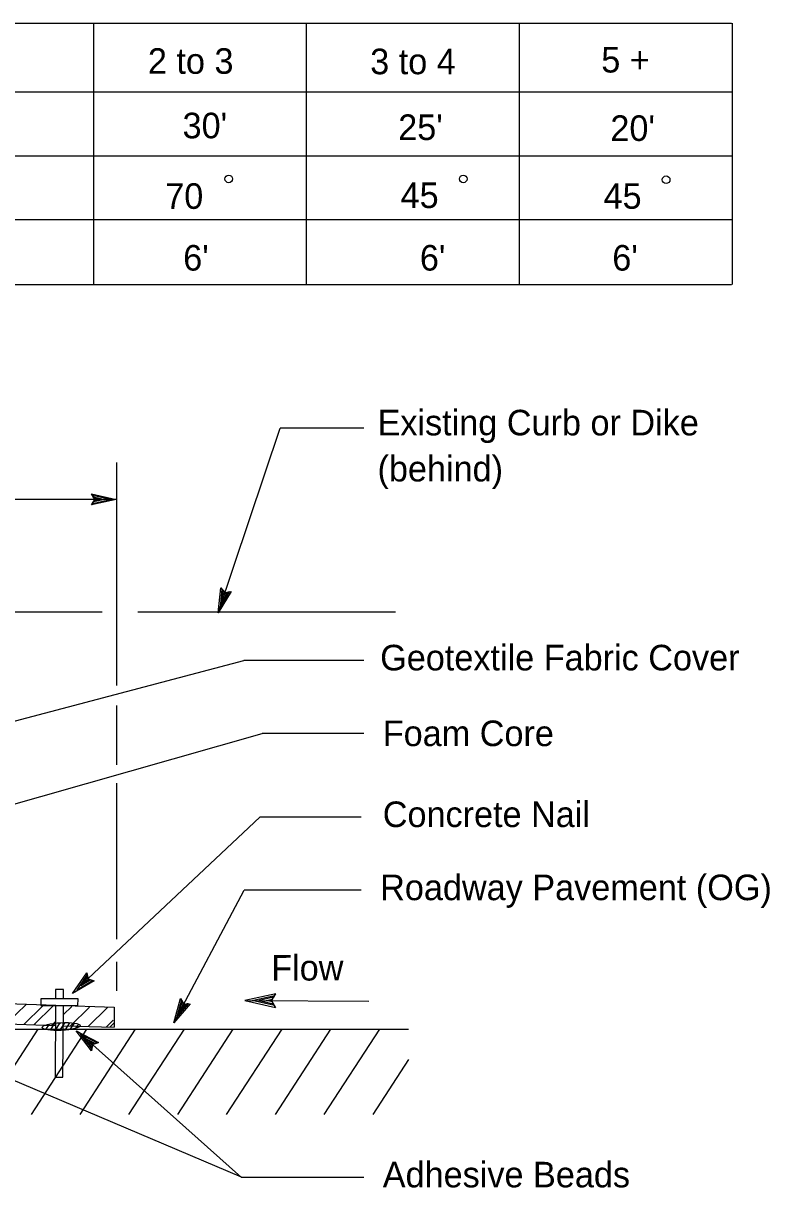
# Model space of a CAD drawing. Extents: x 6708945 to 6710368, y 1871409 to 1872338.
# Drawn here: x 6709846.1 to 6710021.1, y 1872053.9 to 1872327.1 of the extents above; entities that cross this region are included whole.
import ezdxf

# ---------------------------------------------------------------- set-up
doc = ezdxf.new("R2010")
doc.units = 0
for name, color, linetype in [('1 Control', 7, 'Continuous'), ('57 Undefined', 7, 'Continuous'), ('60 Nongeo Data', 7, 'Continuous')]:
    doc.layers.add(name, color=color, linetype=linetype)

msp = doc.modelspace()

# ---------------------------------------------------------------- linework, layer by layer
at = {"layer": '1 Control'}
for p, q in [((6709905.27, 1872099.41), (6709905.27, 1872099.41)), ((6709898.06, 1872097.83), (6709898.06, 1872097.83)), ((6709905.26, 1872096.21), (6709905.26, 1872096.21))]:
    msp.add_line(p, q, dxfattribs=at)
msp.add_lwpolyline([(6709905.27, 1872099.41), (6709898.06, 1872097.83), (6709905.26, 1872096.21), (6709905, 1872096.63), (6709899.73, 1872097.82), (6709905.01, 1872098.99), (6709904.76, 1872098.56), (6709901.38, 1872097.82), (6709904.75, 1872097.06), (6709904.49, 1872097.49), (6709903.04, 1872097.81), (6709904.5, 1872098.14), (6709904.3, 1872097.81), (6709905.26, 1872096.21), (6709904.3, 1872097.81)], close=True, dxfattribs=at)
at = {"layer": '57 Undefined'}
for p, q in [((6709550.84, 1872327.05), (6710012.14, 1872327.05)), ((6709862.61, 1872265.76), (6709862.61, 1872327.05)), ((6709912.53, 1872265.76), (6709912.53, 1872327.05)), ((6709962.45, 1872265.76), (6709962.45, 1872327.05)), ((6710012.37, 1872265.76), (6710012.37, 1872327.05)), ((6709627.72, 1872310.96), (6709893.03, 1872310.96)), ((6709649.9, 1872310.96), (6709915.21, 1872310.96)), ((6709863.83, 1872311), (6709940.81, 1872311)), ((6709914.87, 1872311), (6709991.86, 1872311)), ((6709915.93, 1872311), (6710012.14, 1872311)), ((6709550.84, 1872295.98), (6710012.14, 1872295.98)), ((6709550.73, 1872281.01), (6709916.77, 1872281.01)), ((6709855.9, 1872281.06), (6709859.86, 1872281.06)), ((6709915.93, 1872281.05), (6710012.14, 1872281.05)), ((6709916.63, 1872281.05), (6709993.62, 1872281.05)), ((6709550.84, 1872265.76), (6710012.14, 1872265.76)), ((6709891.8, 1872188.72), (6709906.29, 1872232.1)), ((6709925.94, 1872232.1), (6709906.29, 1872232.1)), ((6709867.99, 1872182.94), (6709867.99, 1872224.04)), ((6709867.87, 1872215.36), (6709800.03, 1872215.36)), ((6709867.99, 1872171.7), (6709867.99, 1872186.66)), ((6709768.13, 1872143.4), (6709897.78, 1872177.59)), ((6709925.94, 1872177.59), (6709897.78, 1872177.59)), ((6709867.99, 1872153.09), (6709867.99, 1872167.05)), ((6709760.18, 1872120.13), (6709902.07, 1872160.44)), ((6709925.94, 1872160.44), (6709902.07, 1872160.44)), ((6709867.99, 1872112.2), (6709867.99, 1872148.76)), ((6709859.97, 1872101.75), (6709901.55, 1872140.84)), ((6709925.32, 1872140.84), (6709901.55, 1872140.84)), ((6709881.39, 1872092.57), (6709897.85, 1872123.69)), ((6709925.32, 1872123.69), (6709897.85, 1872123.69)), ((6709867.99, 1872100.09), (6709867.99, 1872106.88)), ((6709897.25, 1872056.34), (6709816.57, 1872090.62)), ((6709897.27, 1872056.32), (6709858.76, 1872090.59)), ((6709925.94, 1872056.32), (6709897.27, 1872056.32))]:
    msp.add_line(p, q, dxfattribs=at)
for centre in [(6709894.25, 1872290.55), (6709949.25, 1872290.55), (6709996.84, 1872290.34)]:
    msp.add_circle(centre, 0.897, dxfattribs=at)
at = {"layer": '60 Nongeo Data'}
for p, q in [((6709862.11, 1872216.65), (6709862.11, 1872216.65)), ((6709862.11, 1872214.08), (6709862.11, 1872214.08)), ((6709867.87, 1872215.36), (6709867.87, 1872215.36)), ((6709892.41, 1872194.59), (6709892.41, 1872194.59)), ((6709894.85, 1872193.78), (6709894.85, 1872193.78)), ((6709864.57, 1872188.9), (6709805.77, 1872188.9)), ((6709933.37, 1872188.9), (6709872.97, 1872188.9)), ((6709891.8, 1872188.72), (6709891.8, 1872188.72)), ((6709860.96, 1872104.3), (6709860.96, 1872104.3)), ((6709862.72, 1872102.43), (6709862.72, 1872102.43)), ((6709857.64, 1872099.43), (6709857.64, 1872099.43)), ((6709816.28, 1872098.07), (6709867.42, 1872096.25)), ((6709846.76, 1872096.91), (6709842.25, 1872092.46)), ((6709850.67, 1872096.55), (6709846.22, 1872092.16)), ((6709853.05, 1872096.54), (6709848.66, 1872092.21)), ((6709857.45, 1872096.43), (6709855.54, 1872094.55)), ((6709882.96, 1872098.25), (6709882.96, 1872098.25)), ((6709885.22, 1872097.06), (6709885.22, 1872097.06)), ((6709898.56, 1872097.79), (6709927.08, 1872097.68)), ((6709861.58, 1872096.24), (6709857.12, 1872091.84)), ((6709865.81, 1872096.14), (6709861.32, 1872091.71)), ((6709867.42, 1872096.25), (6709867.39, 1872091.53)), ((6709795.95, 1872091.07), (6709936.43, 1872091.07)), ((6709814.06, 1872093.29), (6709853.57, 1872091.92)), ((6709849.45, 1872091.07), (6709836.44, 1872071.04)), ((6709860.9, 1872091.07), (6709847.89, 1872071.04)), ((6709850.63, 1872091.75), (6709850.46, 1872091.48)), ((6709852.12, 1872092.27), (6709851.3, 1872091.01)), ((6709853.39, 1872092.47), (6709852.34, 1872090.85)), ((6709853.52, 1872092.79), (6709852.62, 1872091.9)), ((6709854.61, 1872092.58), (6709853.45, 1872090.79)), ((6709853.56, 1872091.94), (6709853.5, 1872091.88)), ((6709855.78, 1872092.63), (6709854.6, 1872090.8)), ((6709855.57, 1872091.88), (6709867.39, 1872091.53)), ((6709856.91, 1872092.6), (6709855.79, 1872090.87)), ((6709858, 1872092.51), (6709857.03, 1872091.02)), ((6709858.99, 1872092.28), (6709858.35, 1872091.29)), ((6709872.34, 1872091.07), (6709859.34, 1872071.04)), ((6709867.18, 1872093.22), (6709865.53, 1872091.59)), ((6709867.34, 1872092.49), (6709866.4, 1872091.56)), ((6709883.79, 1872091.07), (6709870.78, 1872071.04)), ((6709881.39, 1872092.57), (6709881.39, 1872092.57)), ((6709895.24, 1872091.07), (6709882.23, 1872071.04)), ((6709906.68, 1872091.07), (6709893.68, 1872071.04)), ((6709918.13, 1872091.07), (6709905.12, 1872071.04)), ((6709929.58, 1872091.07), (6709916.57, 1872071.04)), ((6709858.5, 1872090.69), (6709858.5, 1872090.69)), ((6709862.1, 1872086.02), (6709862.1, 1872086.02)), ((6709863.74, 1872087.98), (6709863.74, 1872087.98)), ((6709936.43, 1872083.99), (6709928.02, 1872071.04))]:
    msp.add_line(p, q, dxfattribs=at)
for points in [[(6709862.11, 1872216.65), (6709867.87, 1872215.36), (6709862.11, 1872214.08), (6709862.31, 1872214.42), (6709866.53, 1872215.36), (6709862.31, 1872216.31), (6709862.51, 1872215.97), (6709865.22, 1872215.36), (6709862.52, 1872214.76), (6709862.72, 1872215.1), (6709863.89, 1872215.36), (6709862.72, 1872215.62), (6709862.88, 1872215.36), (6709862.11, 1872214.08), (6709862.88, 1872215.36)], [(6709894.85, 1872193.78), (6709891.8, 1872188.72), (6709892.41, 1872194.59), (6709892.67, 1872194.29), (6709892.22, 1872189.99), (6709894.46, 1872193.69), (6709894.07, 1872193.61), (6709892.64, 1872191.24), (6709892.93, 1872193.99), (6709893.19, 1872193.69), (6709893.06, 1872192.5), (6709893.68, 1872193.52), (6709893.38, 1872193.46), (6709892.41, 1872194.59), (6709893.38, 1872193.46)], [(6709862.72, 1872102.43), (6709857.64, 1872099.43), (6709860.96, 1872104.3), (6709861.05, 1872103.91), (6709858.61, 1872100.34), (6709862.34, 1872102.54), (6709861.95, 1872102.65), (6709859.57, 1872101.24), (6709861.13, 1872103.52), (6709861.21, 1872103.14), (6709860.54, 1872102.15), (6709861.57, 1872102.76), (6709861.28, 1872102.84), (6709860.96, 1872104.3), (6709861.28, 1872102.84)], [(6709858.91, 1872098.18), (6709850.18, 1872098.24), (6709850.17, 1872096.67), (6709858.9, 1872096.61)], [(6709885.22, 1872097.06), (6709881.39, 1872092.57), (6709882.96, 1872098.25), (6709883.16, 1872097.91), (6709882.01, 1872093.75), (6709884.83, 1872097.04), (6709884.43, 1872097.02), (6709882.63, 1872094.91), (6709883.37, 1872097.57), (6709883.57, 1872097.23), (6709883.26, 1872096.08), (6709884.03, 1872096.99), (6709883.73, 1872096.98), (6709882.96, 1872098.25), (6709883.73, 1872096.98)], [(6709862.1, 1872086.02), (6709858.5, 1872090.69), (6709863.75, 1872087.98), (6709863.37, 1872087.85), (6709859.53, 1872089.84), (6709862.17, 1872086.41), (6709862.23, 1872086.8), (6709860.54, 1872088.99), (6709862.99, 1872087.72), (6709862.62, 1872087.59), (6709861.56, 1872088.14), (6709862.29, 1872087.19), (6709862.34, 1872087.5), (6709863.75, 1872087.98), (6709862.34, 1872087.5)]]:
    msp.add_lwpolyline(points, close=True, dxfattribs=at)
for points in [[(6709855.5, 1872098.2), (6709855.52, 1872100.36), (6709853.65, 1872100.37), (6709853.64, 1872098.21)], [(6709853.63, 1872096.68), (6709853.52, 1872079.81), (6709855.38, 1872079.8), (6709855.49, 1872096.61)]]:
    msp.add_lwpolyline(points, dxfattribs=at)
msp.add_ellipse((6709854.94, 1872091.71), major_axis=(4.48, 0.22), ratio=0.199687, dxfattribs=at)

# ---------------------------------------------------------------- texts
at = {"layer": '57 Undefined'}
for s, p in [('2 to 3', (6709875.3, 1872315.2)), ('3 to 4', (6709927.43, 1872315.1)), ('5 +', (6709981.63, 1872315.5)), ("30'", (6709883.43, 1872300.07)), ("25'", (6709934, 1872299.67)), ("20'", (6709983.76, 1872299.45)), ('70', (6709879.36, 1872283.52)), ('45', (6709934.56, 1872283.71)), ('45', (6709982.16, 1872283.54)), ("6'", (6709883.58, 1872269.04)), ("6'", (6709939.08, 1872269.04)), ("6'", (6709984.21, 1872269.04)), ('Existing Curb or Dike', (6709929.15, 1872230.38)), ('(behind)', (6709929.15, 1872219.58)), ('Geotextile Fabric Cover', (6709929.77, 1872175.25)), ('Foam Core', (6709930.38, 1872157.49)), ('Concrete Nail', (6709930.38, 1872138.5)), ('Roadway Pavement (OG)', (6709929.77, 1872121.35)), ('Adhesive Beads', (6709930.38, 1872053.98))]:
    msp.add_text(s, height=6, dxfattribs=at).set_placement(p)
msp.add_text('Flow', height=6, rotation=0.1223, dxfattribs=at).set_placement((6709904.22, 1872102.48))

doc.saveas('drawing.dxf')
